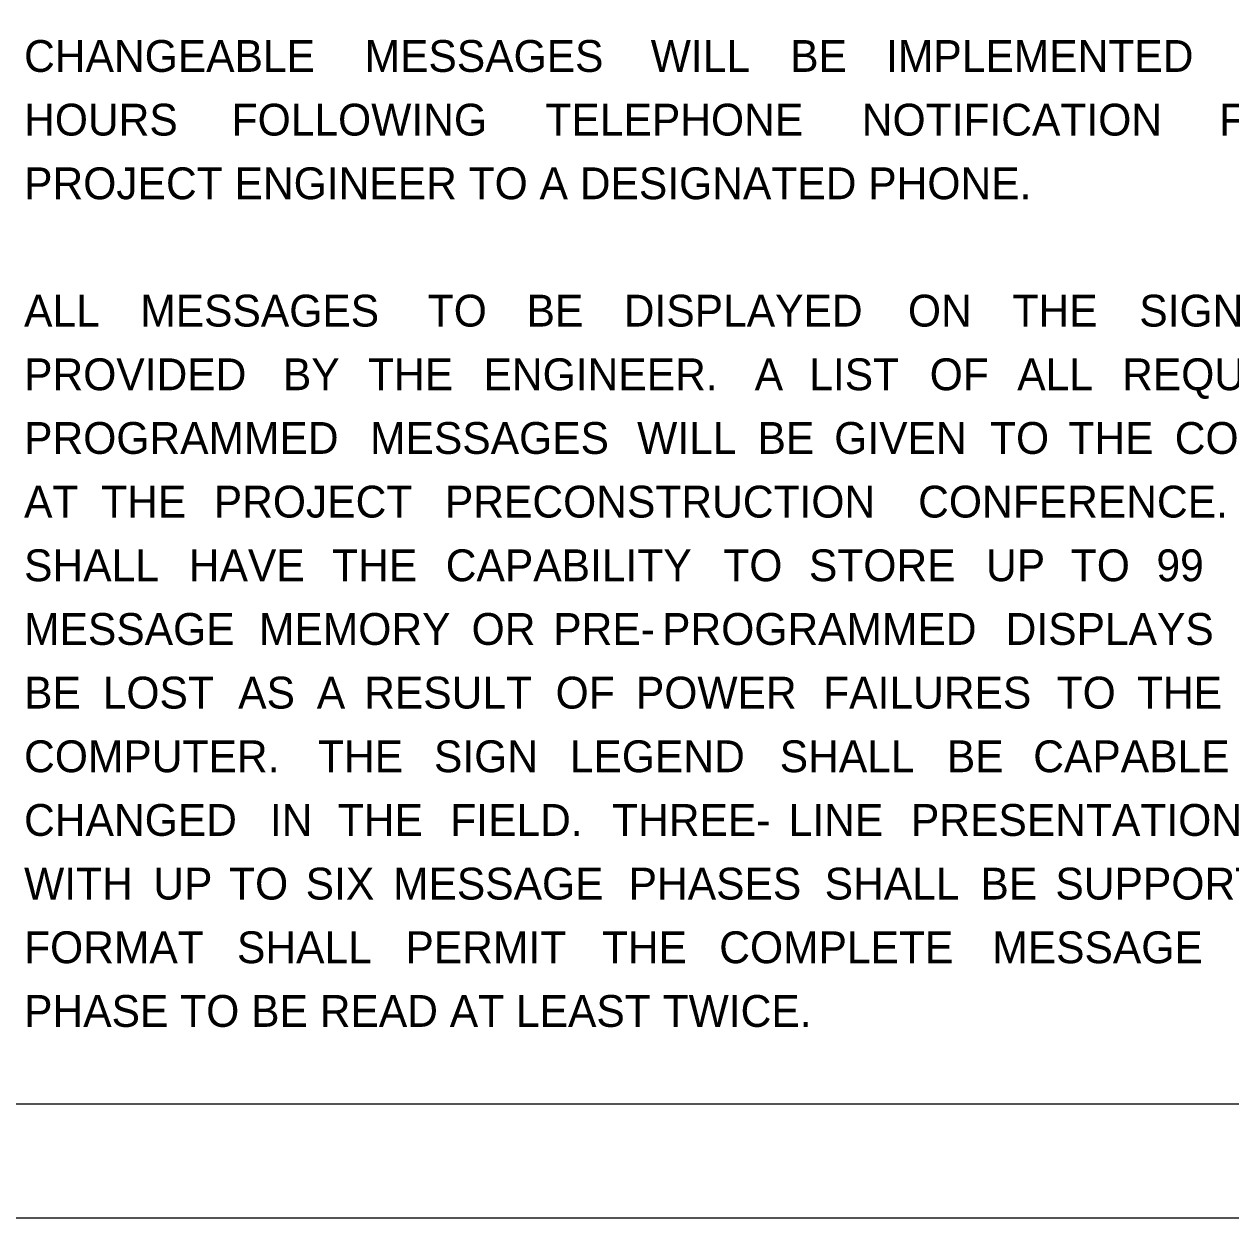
# Model space of a CAD drawing. Extents: x 0 to 34, y 0 to 22.
# Drawn here: x 24.66 to 29.97, y 0 to 5.25 of the extents above; entities that cross this region are included whole.
import ezdxf

# ---------------------------------------------------------------- set-up
doc = ezdxf.new("R2010")
doc.units = 0
for name, color, linetype in [('SH_Border', 7, 'Continuous'), ('SH_Cut_Line', 7, 'Continuous'), ('SH_Text', 7, 'Continuous')]:
    doc.layers.add(name, color=color, linetype=linetype)

msp = doc.modelspace()

# ---------------------------------------------------------------- linework, layer by layer
at = {"layer": 'SH_Border'}
msp.add_lwpolyline([(1.5, 21.5), (33.5, 21.5), (33.5, 0.5), (1.5, 0.5)], close=True, dxfattribs=at)
at = {"layer": 'SH_Cut_Line'}
msp.add_lwpolyline([(0, 0), (34, 0), (34, 22), (0, 22)], close=True, dxfattribs=at)

# ---------------------------------------------------------------- texts
at = {"layer": 'SH_Text'}
for s, p in [('CHANGEABLE ', (24.66, 5.04)), ('MESSAGES ', (26.1579, 5.04)), ('WILL ', (27.4166, 5.04)), ('BE ', (28.0301, 5.04)), ('IMPLEMENTED ', (28.4518, 5.04)), ('HOURS ', (24.66, 4.76)), ('FOLLOWING ', (25.5731, 4.76)), ('TELEPHONE ', (26.9534, 4.76)), ('NOTIFICATION ', (28.3451, 4.76)), ('FROM ', (29.9173, 4.76)), ('PROJECT ENGINEER TO A DESIGNATED PHONE.', (24.66, 4.48)), ('ALL ', (24.66, 3.92)), ('MESSAGES ', (25.171, 3.92)), ('TO ', (26.4357, 3.92)), ('BE ', (26.8704, 3.92)), ('DISPLAYED ', (27.2979, 3.92)), ('ON ', (28.5481, 3.92)), ('THE ', (29.0081, 3.92)), ('SIGN ', (29.5659, 3.92)), ('PROVIDED ', (24.66, 3.64)), ('BY ', (25.7986, 3.64)), ('THE ', (26.1729, 3.64)), ('ENGINEER. ', (26.681, 3.64)), ('A ', (27.874, 3.64)), ('LIST ', (28.114, 3.64)), ('OF ', (28.6439, 3.64)), ('ALL ', (29.0289, 3.64)), ('REQUIRED ', (29.4901, 3.64)), ('PROGRAMMED ', (24.66, 3.36)), ('MESSAGES ', (26.1821, 3.36)), ('WILL ', (27.3568, 3.36)), ('BE ', (27.8863, 3.36)), ('GIVEN ', (28.2238, 3.36)), ('TO ', (28.9092, 3.36)), ('THE ', (29.2539, 3.36)), ('CONTRACTOR ', (29.7218, 3.36)), ('AT ', (24.66, 3.08)), ('THE ', (24.9992, 3.08)), ('PROJECT ', (25.4943, 3.08)), ('PRECONSTRUCTION ', (26.5111, 3.08)), ('CONFERENCE. ', (28.593, 3.08)), ('SHALL ', (24.66, 2.8)), ('HAVE ', (25.3847, 2.8)), ('THE ', (26.0151, 2.8)), ('CAPABILITY ', (26.5149, 2.8)), ('TO ', (27.736, 2.8)), ('STORE ', (28.1126, 2.8)), ('UP ', (28.8915, 2.8)), ('TO ', (29.2645, 2.8)), ('99 ', (29.6411, 2.8)), ('MESSAGE ', (24.66, 2.52)), ('MEMORY ', (25.6933, 2.52)), ('OR ', (26.6286, 2.52)), ('PRE-', (26.9877, 2.52)), ('PROGRAMMED ', (27.4665, 2.52)), ('DISPLAYS ', (28.9778, 2.52)), ('BE ', (24.66, 2.24)), ('LOST ', (25.0059, 2.24)), ('AS ', (25.6018, 2.24)), ('A ', (25.9477, 2.24)), ('RESULT ', (26.1559, 2.24)), ('OF ', (26.9982, 2.24)), ('POWER ', (27.3513, 2.24)), ('FAILURES ', (28.1753, 2.24)), ('TO ', (29.2023, 2.24)), ('THE ', (29.5554, 2.24)), ('COMPUTER. ', (24.66, 1.96)), ('THE ', (25.9528, 1.96)), ('SIGN ', (26.4632, 1.96)), ('LEGEND ', (27.0605, 1.96)), ('SHALL ', (27.984, 1.96)), ('BE ', (28.7193, 1.96)), ('CAPABLE ', (29.0993, 1.96)), ('CHANGED ', (24.66, 1.68)), ('IN ', (25.7414, 1.68)), ('THE ', (26.0401, 1.68)), ('FIELD. ', (26.5346, 1.68)), ('THREE-', (27.2463, 1.68)), ('LINE ', (28.0233, 1.68)), ('PRESENTATION ', (28.5613, 1.68)), ('WITH ', (24.66, 1.4)), ('UP ', (25.2285, 1.4)), ('TO ', (25.5618, 1.4)), ('SIX ', (25.8988, 1.4)), ('MESSAGE ', (26.2829, 1.4)), ('PHASES ', (27.3193, 1.4)), ('SHALL ', (28.1819, 1.4)), ('BE ', (28.867, 1.4)), ('SUPPORTED. ', (29.1968, 1.4)), ('FORMAT ', (24.66, 1.12)), ('SHALL ', (25.5964, 1.12)), ('PERMIT ', (26.3376, 1.12)), ('THE ', (27.2017, 1.12)), ('COMPLETE ', (27.718, 1.12)), ('MESSAGE ', (28.9191, 1.12)), ('PHASE TO BE READ AT LEAST TWICE.', (24.66, 0.84))]:
    msp.add_text(s, height=0.14, dxfattribs=at).set_placement(p)

doc.saveas('drawing.dxf')
